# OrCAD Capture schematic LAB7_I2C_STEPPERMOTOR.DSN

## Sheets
1 lab7ece230winter2016-17: size A
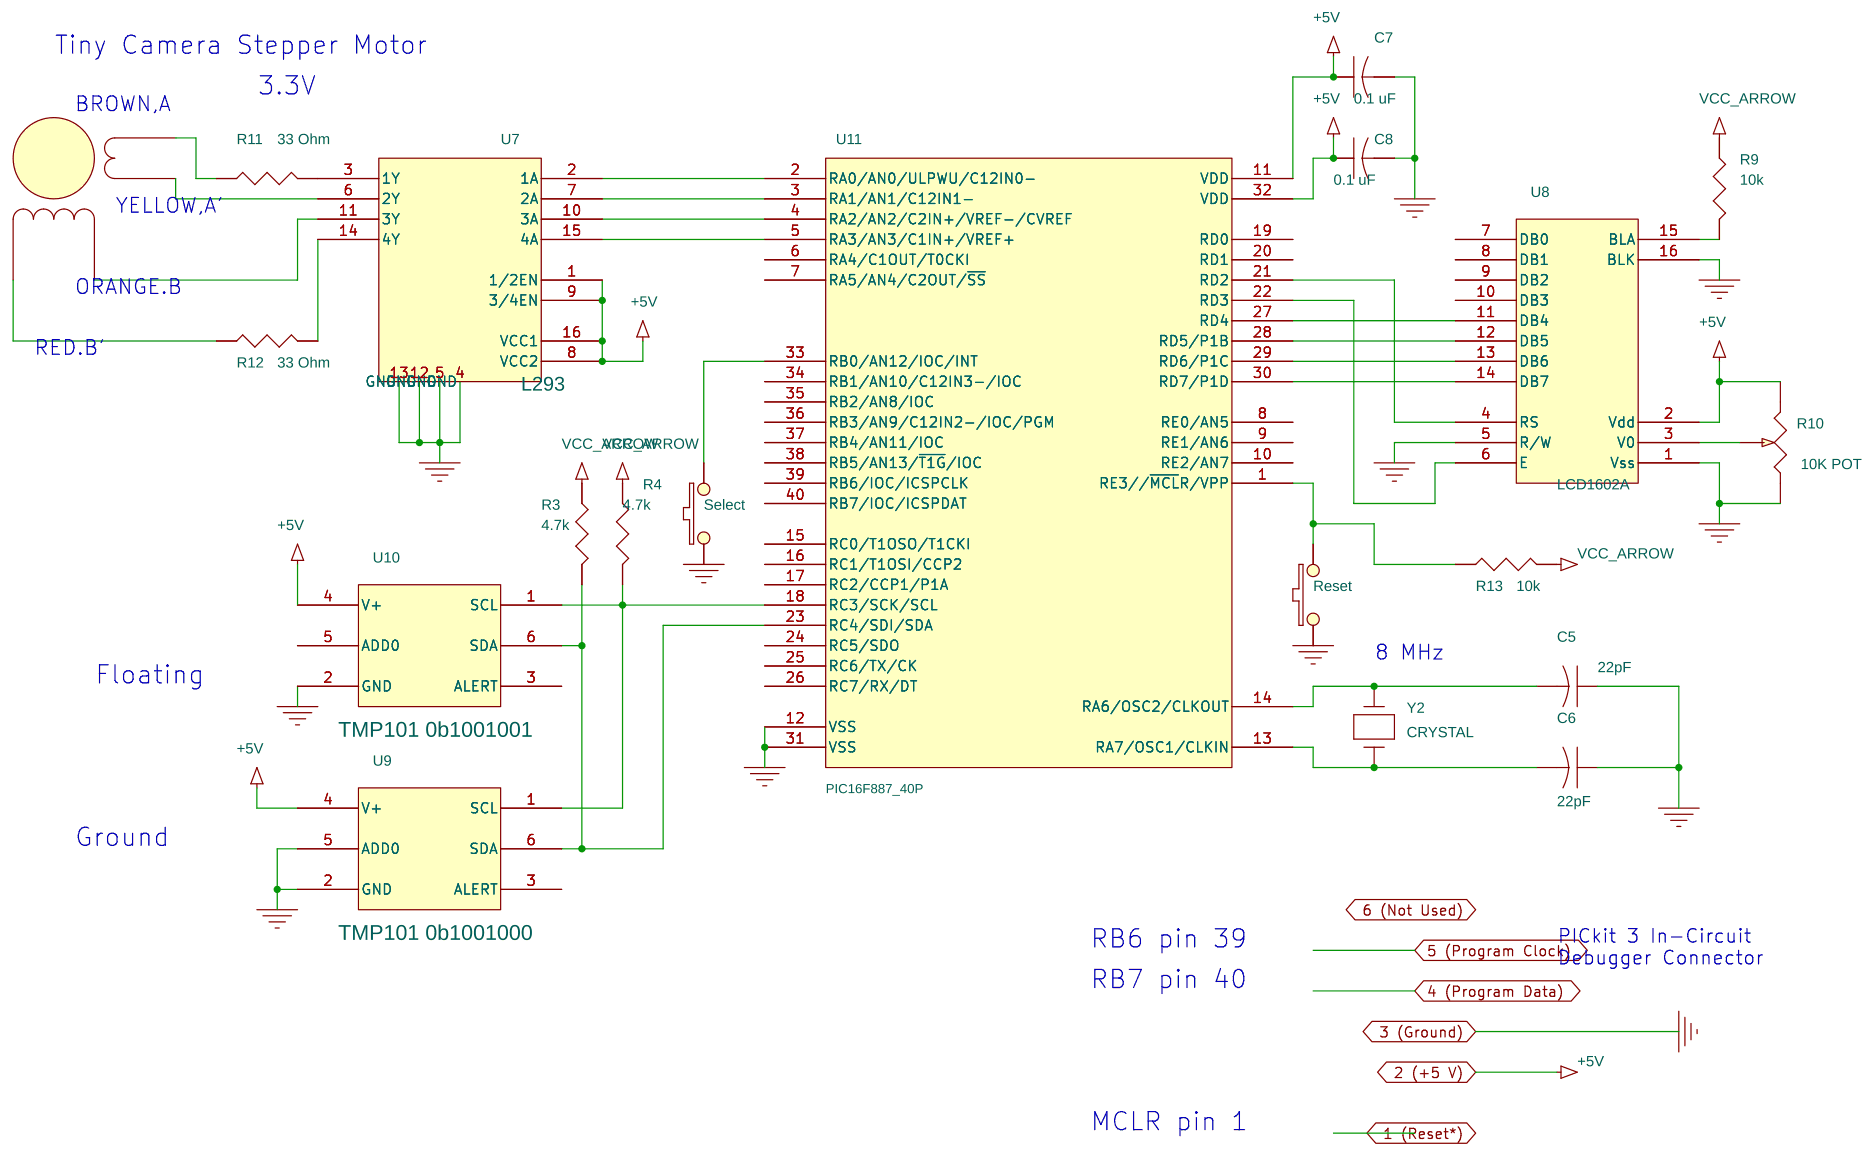
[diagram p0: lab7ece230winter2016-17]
2 lab7: size A; rev: 1
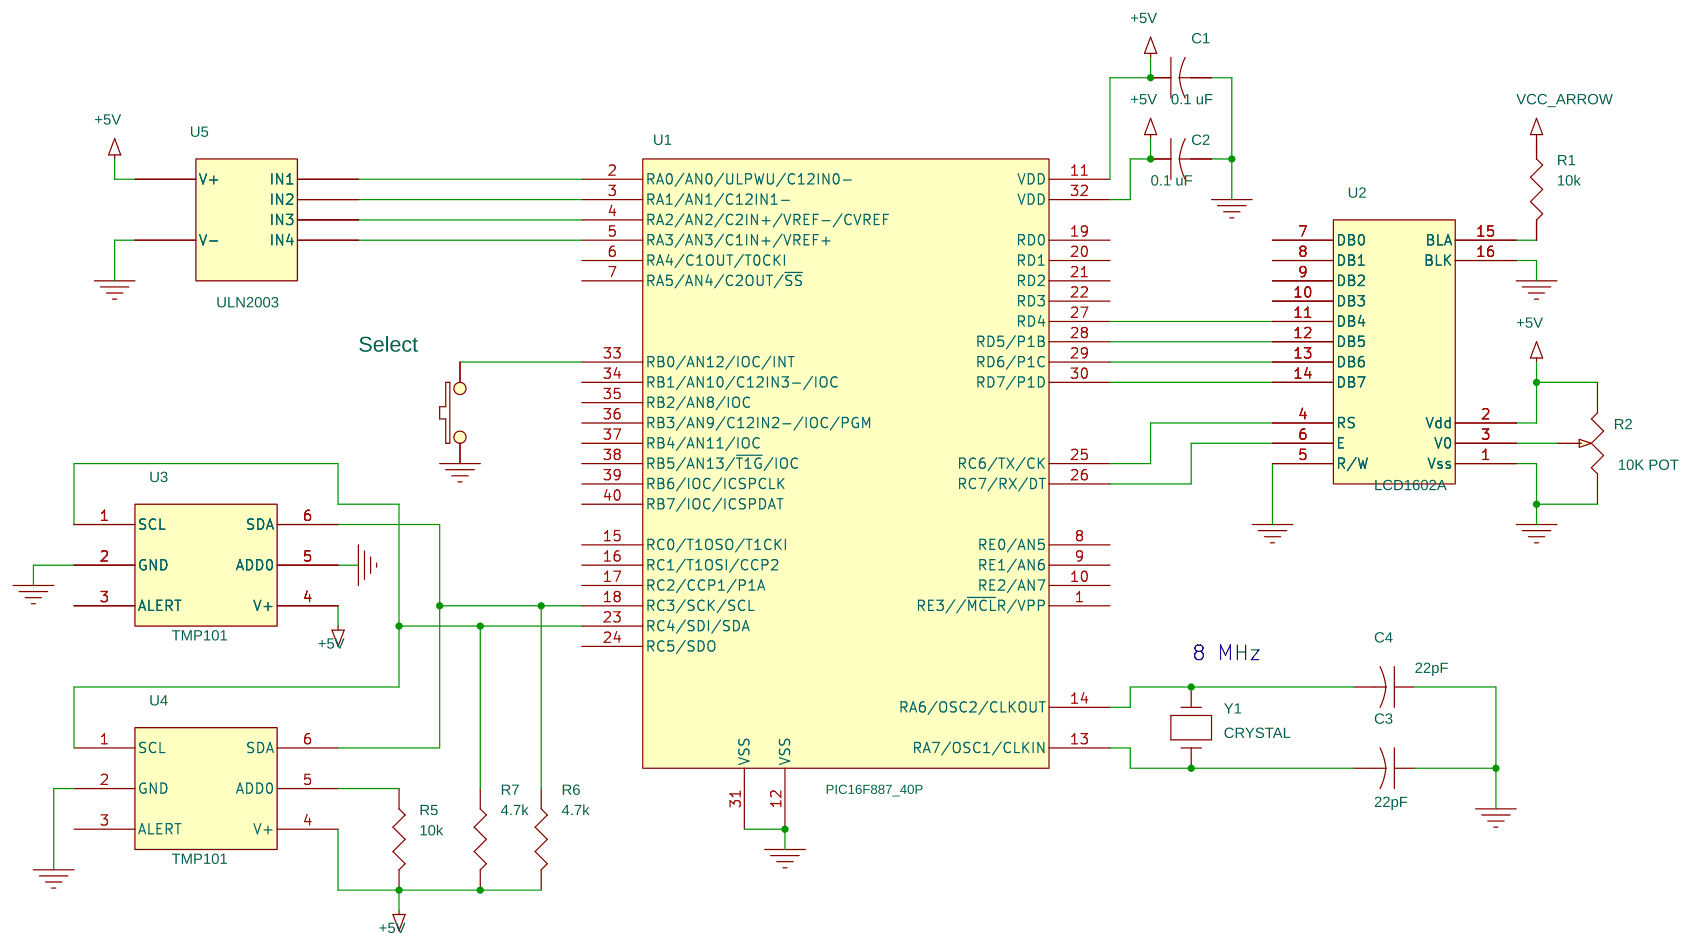
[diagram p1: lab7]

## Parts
sheet lab7
C1  0.1 uF
C2  0.1 uF
C3  22pF
C4  22pF
R1  10k
R2  10K POT
R5  10k
R6  4.7k
R7  4.7k
U1  PIC16F887_40P
U2  LCD1602A
U3  TMP101
U4  TMP101
U5  ULN2003
Y1  CRYSTAL
sheet lab7ece230winter2016-17
C5  22pF
C6  22pF
C7  0.1 uF
C8  0.1 uF
R3  4.7k
R4  4.7k
R9  10k
R10  10K POT
R11  33 Ohm
R12  33 Ohm
R13  10k
Reset  SW PUSHBUTTON
Select  SW PUSHBUTTON
Select#2  SW PUSHBUTTON
Symbol Technologies 12-02485-03  MOTOR STEPPER
U7  L293
U8  LCD1602A
U9  TMP101 0b1001000
U10  TMP101 0b1001001
U11  PIC16F887_40P
Y2  CRYSTAL

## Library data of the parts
C1 C2 C7 C8 = C
C3-C6 = CAP
R1 R3-R7 R9 R11-R13 = R
R2 R10 = POT
U1 = PIC16F887_2: ICA_MFR_NAME: Microchip; ICA_PARTNUM: $$48491116942$$PIC16F887-I/P; Part Number: TMP-13
U2 = LCD1602A_0
U3 = TMP101_1
U4 = TMP101_2
U5 = stepper_motor_driver_board
Y1 Y2 = CRYSTAL
Reset Select Select#2 = SW_PUSHBUTTON
Symbol Technologies 12-02485-03 = MOTOR_STEPPER_1
U7 = L293_2
U8 = LCD1602A_0_v2
U9 U10 = TMP101
U11 = PIC16F887_0_v2: ICA_MFR_NAME: Microchip; ICA_PARTNUM: $$48491116942$$PIC16F887-I/P; Part Number: TMP-13

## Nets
+5V: C1.1 C2.1 C7.1 C8.1 R1.1 R2.3(B) R3.1 R4.1 R5.2 R6.2 R7.2 R9.1 R10.3(B) R13.2 U1.11(VDD) U1.32(VDD) U2.2(Vdd) U3.4(V+) U4.4(V+) U5.V+ U7.1(1/2EN) U7.8(VCC2) U7.9(3/4EN) U7.16(VCC1) U8.2(Vdd) U9.4(V+) U10.4(V+) U11.11(VDD) U11.32(VDD)
GND: C1.2 C2.2 C3.1 C4.1 C5.1 C6.1 C7.2 C8.2 R2.1(A) R10.1(A) Reset.2 Select.2 Select#2.2 U1.12(VSS) U1.31(VSS) U2.1(Vss) U2.5(R/W) U2.16(BLK) U3.2(GND) U3.5(ADD0) U4.2(GND) U5.V- U7.4(GND) U7.5(GND) U7.12(GND) U7.13(GND) U8.1(Vss) U8.5(R/W) U8.16(BLK) U9.2(GND) U9.5(ADD0) U10.2(GND) U11.12(VSS) U11.31(VSS)
N00531: U1.27(RD4) U2.11(DB4)
N00533: U1.28(RD5/P1B) U2.12(DB5)
N00535: U1.29(RD6/P1C) U2.13(DB6)
N00537: U1.30(RD7/P1D) U2.14(DB7)
N00555: R2.2(WIPER) U2.3(V0)
N00557: R1.2 U2.15(BLA)
N00585: C3.2 U1.13(RA7/OSC1/CLKIN) Y1.2
N00593: C4.2 U1.14(RA6/OSC2/CLKOUT) Y1.1
N00601: U1.2(RA0/AN0/ULPWU/C12IN0-) U5.IN1
N00603: U1.3(RA1/AN1/C12IN1-) U5.IN2
N00605: U1.4(RA2/AN2/C2IN+/VREF-/CVREF) U5.IN3
N00607: U1.5(RA3/AN3/C1IN+/VREF+) U5.IN4
N00611: Select.1 U1.33(RB0/AN12/IOC/INT)
N02299: U1.25(RC6/TX/CK) U2.4(RS)
N02310: U1.26(RC7/RX/DT) U2.6(E)
N02598: R6.1 U1.18(RC3/SCK/SCL) U3.6(SDA) U4.6(SDA)
N02611: R7.1 U1.23(RC4/SDI/SDA) U3.1(SCL) U4.1(SCL)
N04722: R5.1 U4.5(ADD0)
N82695: U8.11(DB4) U11.27(RD4)
N82699: U8.12(DB5) U11.28(RD5/P1B)
N82703: U8.13(DB6) U11.29(RD6/P1C)
N82707: U8.14(DB7) U11.30(RD7/P1D)
N82711: U8.4(RS) U11.21(RD2)
N82719: U8.6(E) U11.22(RD3)
N82739: R10.2(WIPER) U8.3(V0)
N82743: R9.2 U8.15(BLA)
N82747: R4.2 U9.1(SCL) U10.1(SCL) U11.18(RC3/SCK/SCL)
N82775: R3.2 U9.6(SDA) U10.6(SDA) U11.23(RC4/SDI/SDA)
N82799: C6.2 U11.13(RA7/OSC1/CLKIN) Y2.2
N82815: C5.2 U11.14(RA6/OSC2/CLKOUT) Y2.1
N82831: Select#2.1 U11.33(RB0/AN12/IOC/INT)
N82917: R12.1 Symbol Technologies 12-02485-03.6
N82925: U7.7(2A) U11.3(RA1/AN1/C12IN1-)
N82929: U7.15(4A) U11.5(RA3/AN3/C1IN+/VREF+)
N83017: U7.10(3A) U11.4(RA2/AN2/C2IN+/VREF-/CVREF)
N83021: U7.2(1A) U11.2(RA0/AN0/ULPWU/C12IN0-)
N86317: Symbol Technologies 12-02485-03.4 U7.11(3Y)
N88807: R11.1 Symbol Technologies 12-02485-03.1
N88868: Symbol Technologies 12-02485-03.3 U7.6(2Y)
N88898: R12.2 U7.14(4Y)
N89985: R13.1 Reset.1 U11.1(RE3//~{MCL}R/VPP)
N91575: R11.2 U7.3(1Y)

Not connected (* = marked no-connect by the designer): U1 1(RE3//~{MCL}R/VPP) 6(RA4/C1OUT/T0CKI) 7(RA5/AN4/C2OUT/~{SS}) 8(RE0/AN5) 9(RE1/AN6) 10(RE2/AN7) 15(RC0/T1OSO/T1CKI) 16(RC1/T1OSI/CCP2) 17(RC2/CCP1/P1A) 19(RD0) 20(RD1) 21(RD2) 22(RD3) 24(RC5/SDO) 34(RB1/AN10/C12IN3-/IOC) 35(RB2/AN8/IOC) 36(RB3/AN9/C12IN2-/IOC/PGM) 37(RB4/AN11/IOC) 38(RB5/AN13/~{T1G}/IOC) 39(RB6/IOC/ICSPCLK) 40(RB7/IOC/ICSPDAT); U2 7(DB0) 8(DB1) 9(DB2) 10(DB3); U3 3(ALERT); U4 3(ALERT); U8 7(DB0) 8(DB1) 9(DB2) 10(DB3); U9 3(ALERT); U10 3(ALERT) 5(ADD0); U11 6(RA4/C1OUT/T0CKI) 7(RA5/AN4/C2OUT/~{SS}) 8(RE0/AN5) 9(RE1/AN6) 10(RE2/AN7) 15(RC0/T1OSO/T1CKI) 16(RC1/T1OSI/CCP2) 17(RC2/CCP1/P1A) 19(RD0) 20(RD1) 24(RC5/SDO) 25(RC6/TX/CK) 26(RC7/RX/DT) 34(RB1/AN10/C12IN3-/IOC) 35(RB2/AN8/IOC) 36(RB3/AN9/C12IN2-/IOC/PGM) 37(RB4/AN11/IOC) 38(RB5/AN13/~{T1G}/IOC) 39(RB6/IOC/ICSPCLK) 40(RB7/IOC/ICSPDAT)

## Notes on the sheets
sheet 1
- Tiny Camera Stepper Motor
- 3.3V
- BROWN,A
- YELLOW,A'
- ORANGE.B
- RED.B'
- 8 MHz
- Floating
- Ground
- RB6 pin 39
- PICkit 3 In-Circuit
  Debugger Connector
- RB7 pin 40
- MCLR pin 1
sheet 2
- 8 MHz
